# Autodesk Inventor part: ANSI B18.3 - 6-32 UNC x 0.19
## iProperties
Comments: To add or edit properties for Autodesk Inventor files, use iProperties.
Created: 2003-10
Part Number: ANSI B18.3 - 6-32 UNC x 0.19
Vendor: Autodesk Inc.
Document SubType Name: Modeling
Designer: jpittman
Material: Default
Description: Hexagon Socket Set Screw - Flat Point
Standard: ANSI B18.3
Manufacturer: Standard
Standards Organization: Custom
Alert: To add or edit properties for Autodesk Inventor files, use iProperties.
Control State: 0
Master: False
Checked Out: False
Shininess: 64.0
Length Units: 11272
Angle Units: 11279
Time Units: 11290
Mass Units: 11286
Length Display Precision: 3
Angle Display Precision: 2
Compacted: True
EGR: 3
Classification: un/spsc 31161505
Density: 0.0
Volumn: 0.0
Area: 0.0
PropertySet Name: Model Information
Author: jpittman
Revision Number: 5
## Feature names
1. Body [Revolution]
2. Chamfer1
3. Slot [Extrusion]
4. Chamfer2
